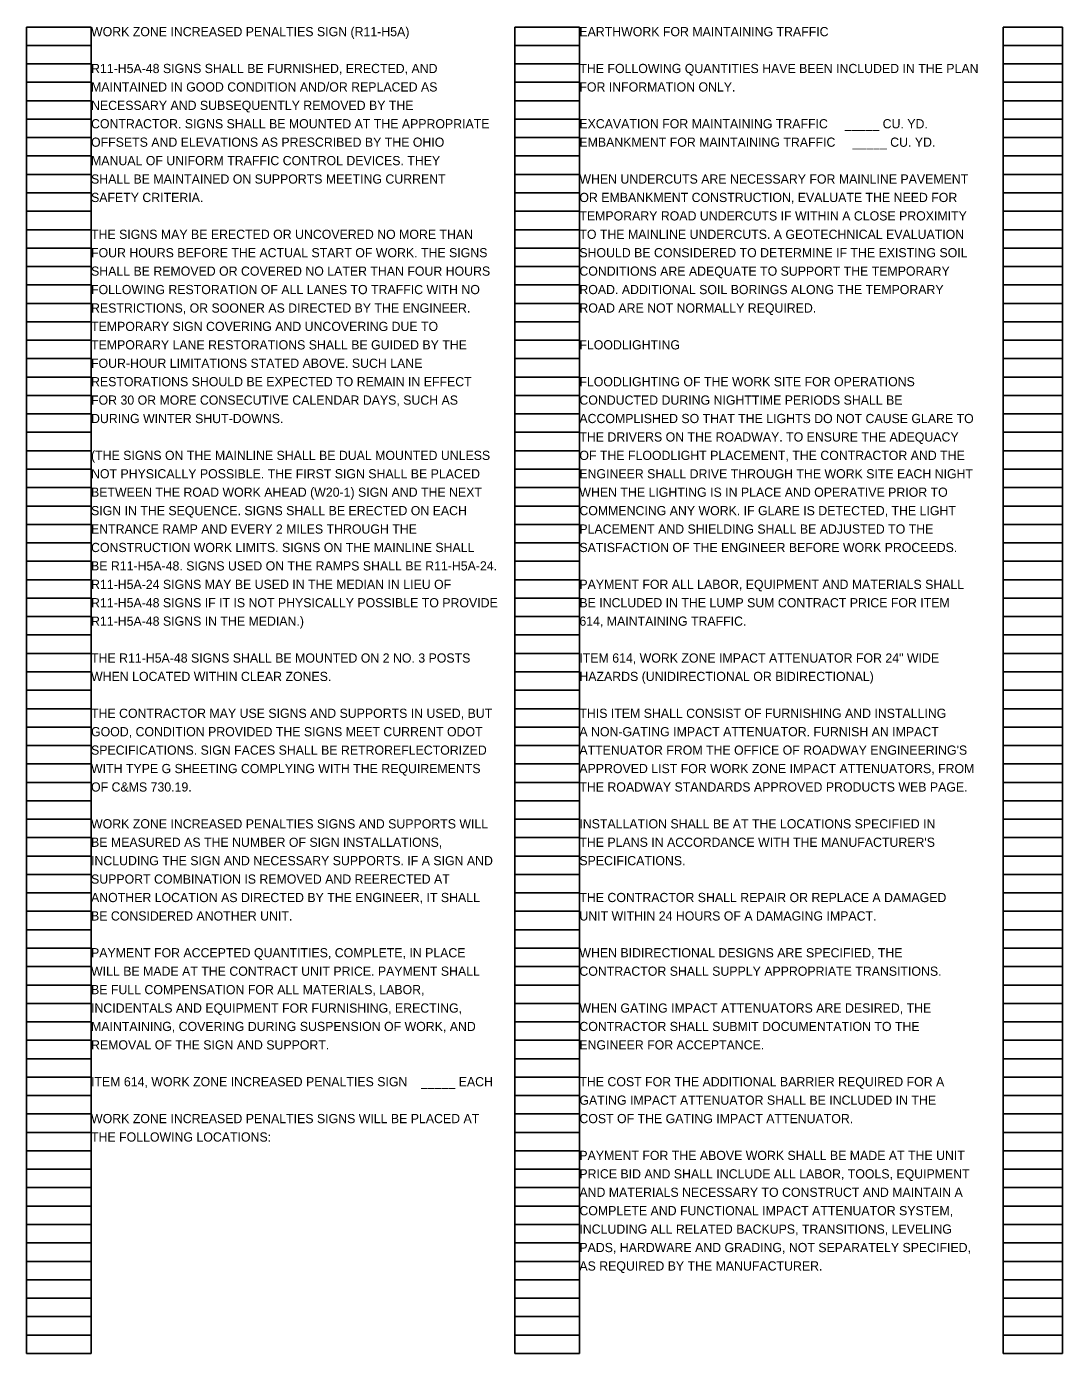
# Model space of a CAD drawing. Extents: x -36 to 68, y -39 to 86.
# Drawn here: x 16.26 to 32, y -23.02 to -2.85 of the extents above; entities that cross this region are included whole.
import ezdxf

# ---------------------------------------------------------------- set-up
doc = ezdxf.new("R2010")
doc.units = 0
doc.layers.add('SH_Data', color=7, linetype='Continuous')
doc.layers.add('SH_Text', color=7, linetype='Continuous')

msp = doc.modelspace()

# ---------------------------------------------------------------- linework, layer by layer
at = {"layer": 'SH_Data'}
for p, q in [((16.26, -23.02), (16.26, -2.86)), ((16.26, -2.86), (17.24, -2.86)), ((17.24, -23.02), (17.24, -2.86)), ((23.68, -23.02), (23.68, -2.86)), ((23.68, -2.86), (24.66, -2.86)), ((24.66, -23.02), (24.66, -2.86)), ((31.1, -23.02), (31.1, -2.86)), ((31.1, -2.86), (32, -2.86)), ((32, -23.02), (32, -2.86)), ((16.26, -3.14), (17.24, -3.14)), ((23.68, -3.14), (24.66, -3.14)), ((31.1, -3.14), (32, -3.14)), ((16.26, -3.42), (17.24, -3.42)), ((23.68, -3.42), (24.66, -3.42)), ((31.1, -3.42), (32, -3.42)), ((16.26, -3.7), (17.24, -3.7)), ((23.68, -3.7), (24.66, -3.7)), ((31.1, -3.7), (32, -3.7)), ((16.26, -3.98), (17.24, -3.98)), ((23.68, -3.98), (24.66, -3.98)), ((31.1, -3.98), (32, -3.98)), ((16.26, -4.26), (17.24, -4.26)), ((23.68, -4.26), (24.66, -4.26)), ((31.1, -4.26), (32, -4.26)), ((16.26, -4.54), (17.24, -4.54)), ((23.68, -4.54), (24.66, -4.54)), ((31.1, -4.54), (32, -4.54)), ((16.26, -4.82), (17.24, -4.82)), ((23.68, -4.82), (24.66, -4.82)), ((31.1, -4.82), (32, -4.82)), ((16.26, -5.1), (17.24, -5.1)), ((23.68, -5.1), (24.66, -5.1)), ((31.1, -5.1), (32, -5.1)), ((16.26, -5.38), (17.24, -5.38)), ((23.68, -5.38), (24.66, -5.38)), ((31.1, -5.38), (32, -5.38)), ((16.26, -5.66), (17.24, -5.66)), ((23.68, -5.66), (24.66, -5.66)), ((31.1, -5.66), (32, -5.66)), ((16.26, -5.94), (17.24, -5.94)), ((23.68, -5.94), (24.66, -5.94)), ((31.1, -5.94), (32, -5.94)), ((16.26, -6.22), (17.24, -6.22)), ((23.68, -6.22), (24.66, -6.22)), ((31.1, -6.22), (32, -6.22)), ((16.26, -6.5), (17.24, -6.5)), ((23.68, -6.5), (24.66, -6.5)), ((31.1, -6.5), (32, -6.5)), ((16.26, -6.78), (17.24, -6.78)), ((23.68, -6.78), (24.66, -6.78)), ((31.1, -6.78), (32, -6.78)), ((16.26, -7.06), (17.24, -7.06)), ((23.68, -7.06), (24.66, -7.06)), ((31.1, -7.06), (32, -7.06)), ((16.26, -7.34), (17.24, -7.34)), ((23.68, -7.34), (24.66, -7.34)), ((31.1, -7.34), (32, -7.34)), ((16.26, -7.62), (17.24, -7.62)), ((23.68, -7.62), (24.66, -7.62)), ((31.1, -7.62), (32, -7.62)), ((16.26, -7.9), (17.24, -7.9)), ((23.68, -7.9), (24.66, -7.9)), ((31.1, -7.9), (32, -7.9)), ((16.26, -8.18), (17.24, -8.18)), ((23.68, -8.18), (24.66, -8.18)), ((31.1, -8.18), (32, -8.18)), ((16.26, -8.46), (17.24, -8.46)), ((23.68, -8.46), (24.66, -8.46)), ((31.1, -8.46), (32, -8.46)), ((16.26, -8.74), (17.24, -8.74)), ((23.68, -8.74), (24.66, -8.74)), ((31.1, -8.74), (32, -8.74)), ((16.26, -9.02), (17.24, -9.02)), ((23.68, -9.02), (24.66, -9.02)), ((31.1, -9.02), (32, -9.02)), ((16.26, -9.3), (17.24, -9.3)), ((23.68, -9.3), (24.66, -9.3)), ((31.1, -9.3), (32, -9.3)), ((16.26, -9.58), (17.24, -9.58)), ((23.68, -9.58), (24.66, -9.58)), ((31.1, -9.58), (32, -9.58)), ((16.26, -9.86), (17.24, -9.86)), ((23.68, -9.86), (24.66, -9.86)), ((31.1, -9.86), (32, -9.86)), ((16.26, -10.14), (17.24, -10.14)), ((23.68, -10.14), (24.66, -10.14)), ((31.1, -10.14), (32, -10.14)), ((16.26, -10.42), (17.24, -10.42)), ((23.68, -10.42), (24.66, -10.42)), ((31.1, -10.42), (32, -10.42)), ((16.26, -10.7), (17.24, -10.7)), ((23.68, -10.7), (24.66, -10.7)), ((31.1, -10.7), (32, -10.7)), ((16.26, -10.98), (17.24, -10.98)), ((23.68, -10.98), (24.66, -10.98)), ((31.1, -10.98), (32, -10.98)), ((16.26, -11.26), (17.24, -11.26)), ((23.68, -11.26), (24.66, -11.26)), ((31.1, -11.26), (32, -11.26)), ((16.26, -11.54), (17.24, -11.54)), ((23.68, -11.54), (24.66, -11.54)), ((31.1, -11.54), (32, -11.54)), ((16.26, -11.82), (17.24, -11.82)), ((23.68, -11.82), (24.66, -11.82)), ((31.1, -11.82), (32, -11.82)), ((16.26, -12.1), (17.24, -12.1)), ((23.68, -12.1), (24.66, -12.1)), ((31.1, -12.1), (32, -12.1)), ((16.26, -12.38), (17.24, -12.38)), ((23.68, -12.38), (24.66, -12.38)), ((31.1, -12.38), (32, -12.38)), ((16.26, -12.66), (17.24, -12.66)), ((23.68, -12.66), (24.66, -12.66)), ((31.1, -12.66), (32, -12.66)), ((16.26, -12.94), (17.24, -12.94)), ((23.68, -12.94), (24.66, -12.94)), ((31.1, -12.94), (32, -12.94)), ((16.26, -13.22), (17.24, -13.22)), ((23.68, -13.22), (24.66, -13.22)), ((31.1, -13.22), (32, -13.22)), ((16.26, -13.5), (17.24, -13.5)), ((23.68, -13.5), (24.66, -13.5)), ((31.1, -13.5), (32, -13.5)), ((16.26, -13.78), (17.24, -13.78)), ((23.68, -13.78), (24.66, -13.78)), ((31.1, -13.78), (32, -13.78)), ((16.26, -14.06), (17.24, -14.06)), ((23.68, -14.06), (24.66, -14.06)), ((31.1, -14.06), (32, -14.06)), ((16.26, -14.34), (17.24, -14.34)), ((23.68, -14.34), (24.66, -14.34)), ((31.1, -14.34), (32, -14.34)), ((16.26, -14.62), (17.24, -14.62)), ((23.68, -14.62), (24.66, -14.62)), ((31.1, -14.62), (32, -14.62)), ((16.26, -14.9), (17.24, -14.9)), ((23.68, -14.9), (24.66, -14.9)), ((31.1, -14.9), (32, -14.9)), ((16.26, -15.18), (17.24, -15.18)), ((23.68, -15.18), (24.66, -15.18)), ((31.1, -15.18), (32, -15.18)), ((16.26, -15.46), (17.24, -15.46)), ((23.68, -15.46), (24.66, -15.46)), ((31.1, -15.46), (32, -15.46)), ((16.26, -15.74), (17.24, -15.74)), ((23.68, -15.74), (24.66, -15.74)), ((31.1, -15.74), (32, -15.74)), ((16.26, -16.02), (17.24, -16.02)), ((23.68, -16.02), (24.66, -16.02)), ((31.1, -16.02), (32, -16.02)), ((16.26, -16.3), (17.24, -16.3)), ((23.68, -16.3), (24.66, -16.3)), ((31.1, -16.3), (32, -16.3)), ((16.26, -16.58), (17.24, -16.58)), ((23.68, -16.58), (24.66, -16.58)), ((31.1, -16.58), (32, -16.58)), ((16.26, -16.86), (17.24, -16.86)), ((23.68, -16.86), (24.66, -16.86)), ((31.1, -16.86), (32, -16.86)), ((16.26, -17.14), (17.24, -17.14)), ((23.68, -17.14), (24.66, -17.14)), ((31.1, -17.14), (32, -17.14)), ((16.26, -17.42), (17.24, -17.42)), ((23.68, -17.42), (24.66, -17.42)), ((31.1, -17.42), (32, -17.42)), ((16.26, -17.7), (17.24, -17.7)), ((23.68, -17.7), (24.66, -17.7)), ((31.1, -17.7), (32, -17.7)), ((16.26, -17.98), (17.24, -17.98)), ((23.68, -17.98), (24.66, -17.98)), ((31.1, -17.98), (32, -17.98)), ((16.26, -18.26), (17.24, -18.26)), ((23.68, -18.26), (24.66, -18.26)), ((31.1, -18.26), (32, -18.26)), ((16.26, -18.54), (17.24, -18.54)), ((23.68, -18.54), (24.66, -18.54)), ((31.1, -18.54), (32, -18.54)), ((16.26, -18.82), (17.24, -18.82)), ((23.68, -18.82), (24.66, -18.82)), ((31.1, -18.82), (32, -18.82)), ((16.26, -19.1), (17.24, -19.1)), ((23.68, -19.1), (24.66, -19.1)), ((31.1, -19.1), (32, -19.1)), ((16.26, -19.38), (17.24, -19.38)), ((23.68, -19.38), (24.66, -19.38)), ((31.1, -19.38), (32, -19.38)), ((16.26, -19.66), (17.24, -19.66)), ((23.68, -19.66), (24.66, -19.66)), ((31.1, -19.66), (32, -19.66)), ((16.26, -19.94), (17.24, -19.94)), ((23.68, -19.94), (24.66, -19.94)), ((31.1, -19.94), (32, -19.94)), ((16.26, -20.22), (17.24, -20.22)), ((23.68, -20.22), (24.66, -20.22)), ((31.1, -20.22), (32, -20.22)), ((16.26, -20.5), (17.24, -20.5)), ((23.68, -20.5), (24.66, -20.5)), ((31.1, -20.5), (32, -20.5)), ((16.26, -20.78), (17.24, -20.78)), ((23.68, -20.78), (24.66, -20.78)), ((31.1, -20.78), (32, -20.78)), ((16.26, -21.06), (17.24, -21.06)), ((23.68, -21.06), (24.66, -21.06)), ((31.1, -21.06), (32, -21.06)), ((16.26, -21.34), (17.24, -21.34)), ((23.68, -21.34), (24.66, -21.34)), ((31.1, -21.34), (32, -21.34)), ((16.26, -21.62), (17.24, -21.62)), ((23.68, -21.62), (24.66, -21.62)), ((31.1, -21.62), (32, -21.62)), ((16.26, -21.9), (17.24, -21.9)), ((23.68, -21.9), (24.66, -21.9)), ((31.1, -21.9), (32, -21.9)), ((16.26, -22.18), (17.24, -22.18)), ((23.68, -22.18), (24.66, -22.18)), ((31.1, -22.18), (32, -22.18)), ((16.26, -22.46), (17.24, -22.46)), ((23.68, -22.46), (24.66, -22.46)), ((31.1, -22.46), (32, -22.46)), ((16.26, -22.74), (17.24, -22.74)), ((23.68, -22.74), (24.66, -22.74)), ((31.1, -22.74), (32, -22.74)), ((16.26, -23.02), (17.24, -23.02)), ((23.68, -23.02), (24.66, -23.02)), ((31.1, -23.02), (32, -23.02))]:
    msp.add_line(p, q, dxfattribs=at)

# ---------------------------------------------------------------- texts
at = {"layer": 'SH_Text'}
for s, p in [('WORK ZONE INCREASED PENALTIES SIGN (R11-H5A)', (17.24, -3)), ('EARTHWORK FOR MAINTAINING TRAFFIC', (24.66, -3)), ('R11-H5A-48 SIGNS SHALL BE FURNISHED, ERECTED, AND', (17.24, -3.56)), ('THE FOLLOWING QUANTITIES HAVE BEEN INCLUDED IN THE PLAN', (24.66, -3.56)), ('MAINTAINED IN GOOD CONDITION AND/OR REPLACED AS', (17.24, -3.84)), ('FOR INFORMATION ONLY.', (24.66, -3.84)), ('NECESSARY AND SUBSEQUENTLY REMOVED BY THE', (17.24, -4.12)), ('CONTRACTOR. SIGNS SHALL BE MOUNTED AT THE APPROPRIATE', (17.24, -4.4)), ('EXCAVATION FOR MAINTAINING TRAFFIC     _____ CU. YD.', (24.66, -4.4)), ('OFFSETS AND ELEVATIONS AS PRESCRIBED BY THE OHIO', (17.24, -4.68)), ('EMBANKMENT FOR MAINTAINING TRAFFIC     _____ CU. YD.', (24.66, -4.68)), ('MANUAL OF UNIFORM TRAFFIC CONTROL DEVICES. THEY', (17.24, -4.96)), ('SHALL BE MAINTAINED ON SUPPORTS MEETING CURRENT', (17.24, -5.24)), ('WHEN UNDERCUTS ARE NECESSARY FOR MAINLINE PAVEMENT', (24.66, -5.24)), ('SAFETY CRITERIA.', (17.24, -5.52)), ('OR EMBANKMENT CONSTRUCTION, EVALUATE THE NEED FOR', (24.66, -5.52)), ('TEMPORARY ROAD UNDERCUTS IF WITHIN A CLOSE PROXIMITY', (24.66, -5.8)), ('THE SIGNS MAY BE ERECTED OR UNCOVERED NO MORE THAN', (17.24, -6.08)), ('TO THE MAINLINE UNDERCUTS. A GEOTECHNICAL EVALUATION', (24.66, -6.08)), ('FOUR HOURS BEFORE THE ACTUAL START OF WORK. THE SIGNS', (17.24, -6.36)), ('SHOULD BE CONSIDERED TO DETERMINE IF THE EXISTING SOIL', (24.66, -6.36)), ('SHALL BE REMOVED OR COVERED NO LATER THAN FOUR HOURS', (17.24, -6.64)), ('CONDITIONS ARE ADEQUATE TO SUPPORT THE TEMPORARY', (24.66, -6.64)), ('FOLLOWING RESTORATION OF ALL LANES TO TRAFFIC WITH NO', (17.24, -6.92)), ('ROAD. ADDITIONAL SOIL BORINGS ALONG THE TEMPORARY', (24.66, -6.92)), ('RESTRICTIONS, OR SOONER AS DIRECTED BY THE ENGINEER.', (17.24, -7.2)), ('ROAD ARE NOT NORMALLY REQUIRED.', (24.66, -7.2)), ('TEMPORARY SIGN COVERING AND UNCOVERING DUE TO', (17.24, -7.48)), ('TEMPORARY LANE RESTORATIONS SHALL BE GUIDED BY THE', (17.24, -7.76)), ('FLOODLIGHTING', (24.66, -7.76)), ('FOUR-HOUR LIMITATIONS STATED ABOVE. SUCH LANE', (17.24, -8.04)), ('RESTORATIONS SHOULD BE EXPECTED TO REMAIN IN EFFECT', (17.24, -8.32)), ('FLOODLIGHTING OF THE WORK SITE FOR OPERATIONS', (24.66, -8.32)), ('FOR 30 OR MORE CONSECUTIVE CALENDAR DAYS, SUCH AS', (17.24, -8.6)), ('CONDUCTED DURING NIGHTTIME PERIODS SHALL BE', (24.66, -8.6)), ('DURING WINTER SHUT-DOWNS.', (17.24, -8.88)), ('ACCOMPLISHED SO THAT THE LIGHTS DO NOT CAUSE GLARE TO', (24.66, -8.88)), ('THE DRIVERS ON THE ROADWAY. TO ENSURE THE ADEQUACY', (24.66, -9.16)), ('(THE SIGNS ON THE MAINLINE SHALL BE DUAL MOUNTED UNLESS', (17.24, -9.44)), ('OF THE FLOODLIGHT PLACEMENT, THE CONTRACTOR AND THE', (24.66, -9.44)), ('NOT PHYSICALLY POSSIBLE. THE FIRST SIGN SHALL BE PLACED', (17.24, -9.72)), ('ENGINEER SHALL DRIVE THROUGH THE WORK SITE EACH NIGHT', (24.66, -9.72)), ('BETWEEN THE ROAD WORK AHEAD (W20-1) SIGN AND THE NEXT', (17.24, -10)), ('WHEN THE LIGHTING IS IN PLACE AND OPERATIVE PRIOR TO', (24.66, -10)), ('SIGN IN THE SEQUENCE. SIGNS SHALL BE ERECTED ON EACH', (17.24, -10.28)), ('COMMENCING ANY WORK. IF GLARE IS DETECTED, THE LIGHT', (24.66, -10.28)), ('ENTRANCE RAMP AND EVERY 2 MILES THROUGH THE', (17.24, -10.56)), ('PLACEMENT AND SHIELDING SHALL BE ADJUSTED TO THE', (24.66, -10.56)), ('CONSTRUCTION WORK LIMITS. SIGNS ON THE MAINLINE SHALL', (17.24, -10.84)), ('SATISFACTION OF THE ENGINEER BEFORE WORK PROCEEDS.', (24.66, -10.84)), ('BE R11-H5A-48. SIGNS USED ON THE RAMPS SHALL BE R11-H5A-24.', (17.24, -11.12)), ('R11-H5A-24 SIGNS MAY BE USED IN THE MEDIAN IN LIEU OF', (17.24, -11.4)), ('PAYMENT FOR ALL LABOR, EQUIPMENT AND MATERIALS SHALL', (24.66, -11.4)), ('R11-H5A-48 SIGNS IF IT IS NOT PHYSICALLY POSSIBLE TO PROVIDE', (17.24, -11.68)), ('BE INCLUDED IN THE LUMP SUM CONTRACT PRICE FOR ITEM', (24.66, -11.68)), ('R11-H5A-48 SIGNS IN THE MEDIAN.)', (17.24, -11.96)), ('614, MAINTAINING TRAFFIC.', (24.66, -11.96)), ('THE R11-H5A-48 SIGNS SHALL BE MOUNTED ON 2 NO. 3 POSTS', (17.24, -12.52)), ('ITEM 614, WORK ZONE IMPACT ATTENUATOR FOR 24" WIDE', (24.66, -12.52)), ('WHEN LOCATED WITHIN CLEAR ZONES.', (17.24, -12.8)), ('HAZARDS (UNIDIRECTIONAL OR BIDIRECTIONAL)', (24.66, -12.8)), ('THE CONTRACTOR MAY USE SIGNS AND SUPPORTS IN USED, BUT', (17.24, -13.36)), ('THIS ITEM SHALL CONSIST OF FURNISHING AND INSTALLING', (24.66, -13.36)), ('GOOD, CONDITION PROVIDED THE SIGNS MEET CURRENT ODOT', (17.24, -13.64)), ('A NON-GATING IMPACT ATTENUATOR. FURNISH AN IMPACT', (24.66, -13.64)), ('SPECIFICATIONS. SIGN FACES SHALL BE RETROREFLECTORIZED', (17.24, -13.92)), ("ATTENUATOR FROM THE OFFICE OF ROADWAY ENGINEERING'S", (24.66, -13.92)), ('WITH TYPE G SHEETING COMPLYING WITH THE REQUIREMENTS', (17.24, -14.2)), ('APPROVED LIST FOR WORK ZONE IMPACT ATTENUATORS, FROM', (24.66, -14.2)), ('OF C&MS 730.19.', (17.24, -14.48)), ('THE ROADWAY STANDARDS APPROVED PRODUCTS WEB PAGE.', (24.66, -14.48)), ('WORK ZONE INCREASED PENALTIES SIGNS AND SUPPORTS WILL', (17.24, -15.04)), ('INSTALLATION SHALL BE AT THE LOCATIONS SPECIFIED IN', (24.66, -15.04)), ('BE MEASURED AS THE NUMBER OF SIGN INSTALLATIONS,', (17.24, -15.32)), ("THE PLANS IN ACCORDANCE WITH THE MANUFACTURER'S", (24.66, -15.32)), ('INCLUDING THE SIGN AND NECESSARY SUPPORTS. IF A SIGN AND', (17.24, -15.6)), ('SPECIFICATIONS.', (24.66, -15.6)), ('SUPPORT COMBINATION IS REMOVED AND REERECTED AT', (17.24, -15.88)), ('ANOTHER LOCATION AS DIRECTED BY THE ENGINEER, IT SHALL', (17.24, -16.16)), ('THE CONTRACTOR SHALL REPAIR OR REPLACE A DAMAGED', (24.66, -16.16)), ('BE CONSIDERED ANOTHER UNIT.', (17.24, -16.44)), ('UNIT WITHIN 24 HOURS OF A DAMAGING IMPACT.', (24.66, -16.44)), ('PAYMENT FOR ACCEPTED QUANTITIES, COMPLETE, IN PLACE', (17.24, -17)), ('WHEN BIDIRECTIONAL DESIGNS ARE SPECIFIED, THE', (24.66, -17)), ('WILL BE MADE AT THE CONTRACT UNIT PRICE. PAYMENT SHALL', (17.24, -17.28)), ('CONTRACTOR SHALL SUPPLY APPROPRIATE TRANSITIONS.', (24.66, -17.28)), ('BE FULL COMPENSATION FOR ALL MATERIALS, LABOR,', (17.24, -17.56)), ('INCIDENTALS AND EQUIPMENT FOR FURNISHING, ERECTING,', (17.24, -17.84)), ('WHEN GATING IMPACT ATTENUATORS ARE DESIRED, THE', (24.66, -17.84)), ('MAINTAINING, COVERING DURING SUSPENSION OF WORK, AND', (17.24, -18.12)), ('CONTRACTOR SHALL SUBMIT DOCUMENTATION TO THE', (24.66, -18.12)), ('REMOVAL OF THE SIGN AND SUPPORT.', (17.24, -18.4)), ('ENGINEER FOR ACCEPTANCE.', (24.66, -18.4)), ('ITEM 614, WORK ZONE INCREASED PENALTIES SIGN    _____ EACH', (17.24, -18.96)), ('THE COST FOR THE ADDITIONAL BARRIER REQUIRED FOR A', (24.66, -18.96)), ('GATING IMPACT ATTENUATOR SHALL BE INCLUDED IN THE', (24.66, -19.24)), ('WORK ZONE INCREASED PENALTIES SIGNS WILL BE PLACED AT', (17.24, -19.52)), ('COST OF THE GATING IMPACT ATTENUATOR.', (24.66, -19.52)), ('THE FOLLOWING LOCATIONS:', (17.24, -19.8)), ('PAYMENT FOR THE ABOVE WORK SHALL BE MADE AT THE UNIT', (24.66, -20.08)), ('PRICE BID AND SHALL INCLUDE ALL LABOR, TOOLS, EQUIPMENT', (24.66, -20.36)), ('AND MATERIALS NECESSARY TO CONSTRUCT AND MAINTAIN A', (24.66, -20.64)), ('COMPLETE AND FUNCTIONAL IMPACT ATTENUATOR SYSTEM,', (24.66, -20.92)), ('INCLUDING ALL RELATED BACKUPS, TRANSITIONS, LEVELING', (24.66, -21.2)), ('PADS, HARDWARE AND GRADING, NOT SEPARATELY SPECIFIED,', (24.66, -21.48)), ('AS REQUIRED BY THE MANUFACTURER.', (24.66, -21.76))]:
    msp.add_text(s, height=0.14, dxfattribs=at).set_placement(p)

doc.saveas('drawing.dxf')
